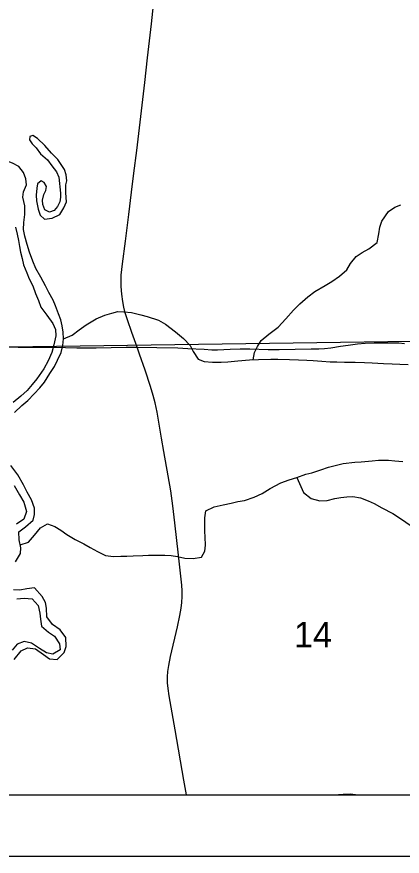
# Model space of a CAD drawing. Extents: x 0 to 34, y 0 to 22.
# Drawn here: x 7.232 to 7.861, y 14 to 15.371 of the extents above; entities that cross this region are included whole.
import ezdxf

# ---------------------------------------------------------------- set-up
doc = ezdxf.new("R2010")
doc.units = 0
for name, color, linetype in [('Default', 7, 'Continuous'), ('GM_X_Interstate_Route', 7, 'Continuous'), ('GM_X_Major_River', 7, 'Continuous'), ('GM_X_Minor_Lake', 7, 'Continuous'), ('GM_X_Minor_River', 7, 'Continuous'), ('GM_X_Section_Text', 7, 'Continuous'), ('GM_X_Township_Road', 7, 'Continuous'), ('SH_Cut_Line', 7, 'Continuous'), ('SH_Data', 7, 'Continuous')]:
    doc.layers.add(name, color=color, linetype=linetype)

msp = doc.modelspace()

# ---------------------------------------------------------------- linework, layer by layer
at = {"layer": 'Default'}
msp.add_lwpolyline([(7.1737, 14.1), (8.2548, 14.1), (8.263, 14.8458), (7.1806, 14.8307)], close=True, dxfattribs=at)
at = {"layer": 'GM_X_Interstate_Route'}
msp.add_lwpolyline([(3.2011, 14.1), (8.2568, 14.1)], dxfattribs=at)
at = {"layer": 'GM_X_Major_River'}
for points in [[(7.242, 15.0762), (7.2431, 15.0852), (7.2482, 15.0966), (7.2471, 15.1065), (7.243, 15.1164), (7.2355, 15.1263), (7.225, 15.1317), (7.214, 15.1364)], [(7.2286, 14.7244), (7.2403, 14.7362), (7.2505, 14.7442), (7.2607, 14.7553), (7.2698, 14.7648), (7.2777, 14.7743), (7.2864, 14.7884), (7.2936, 14.7998), (7.2989, 14.8104), (7.3045, 14.8229), (7.3075, 14.8343), (7.3086, 14.845), (7.3078, 14.856), (7.3063, 14.8662), (7.304, 14.8761), (7.3002, 14.8859), (7.2952, 14.8988), (7.2914, 14.9083), (7.2845, 14.9208), (7.2792, 14.9314), (7.2716, 14.9458), (7.2632, 14.9598), (7.2582, 14.9719), (7.2528, 14.9867), (7.249, 14.9988), (7.2456, 15.0129), (7.2433, 15.0235), (7.244, 15.0352), (7.2455, 15.0482), (7.2454, 15.0622), (7.242, 15.0762)], [(7.23, 15.0272), (7.2327, 15.0162), (7.2353, 15.0056), (7.2365, 14.9958), (7.2384, 14.9863), (7.2411, 14.976), (7.2434, 14.9658), (7.2488, 14.9529), (7.2526, 14.9431), (7.2583, 14.9317), (7.2629, 14.9192), (7.2675, 14.9078), (7.2717, 14.8968), (7.2812, 14.8836), (7.2911, 14.87), (7.2953, 14.8601), (7.2961, 14.8499), (7.2927, 14.835), (7.2894, 14.8225), (7.2837, 14.8092), (7.2762, 14.7959), (7.2652, 14.7799), (7.2573, 14.7704), (7.249, 14.7605), (7.2387, 14.7514), (7.2266, 14.7411)], [(7.23, 14.4808), (7.2383, 14.4942), (7.2391, 14.5036), (7.236, 14.5169), (7.2356, 14.5298), (7.2466, 14.5378), (7.2591, 14.5489), (7.2613, 14.5583), (7.2609, 14.5686), (7.2563, 14.5822), (7.2494, 14.5947), (7.2433, 14.6065), (7.2342, 14.6228), (7.2224, 14.6379)], [(7.2278, 14.6057), (7.2366, 14.5901), (7.2438, 14.578), (7.248, 14.5632), (7.2439, 14.5503), (7.2318, 14.5423)], [(7.2282, 14.3215), (7.2396, 14.3352), (7.2498, 14.3405), (7.2627, 14.3387), (7.2756, 14.3296), (7.2859, 14.3224), (7.298, 14.3213), (7.3098, 14.3327), (7.3131, 14.3426), (7.3123, 14.357), (7.3032, 14.3699), (7.2903, 14.3786), (7.2815, 14.3911), (7.2807, 14.4051), (7.2792, 14.4146), (7.2738, 14.4244), (7.2613, 14.4384), (7.2488, 14.4365), (7.237, 14.4346), (7.2271, 14.4349)], [(7.2321, 14.4205), (7.2442, 14.4213), (7.2575, 14.4202), (7.2674, 14.4092), (7.2701, 14.3971), (7.2709, 14.3873), (7.2725, 14.3759), (7.2839, 14.366), (7.2937, 14.3596), (7.3021, 14.3467), (7.3029, 14.3373), (7.2912, 14.33), (7.2805, 14.3323), (7.2695, 14.3391), (7.2562, 14.3481), (7.2441, 14.3507), (7.2331, 14.3465), (7.2248, 14.3363)]]:
    msp.add_lwpolyline(points, dxfattribs=at)
at = {"layer": 'GM_X_Minor_Lake'}
for points in [[(7.3122, 15.0835), (7.3125, 15.0967), (7.3137, 15.1032), (7.313, 15.113), (7.3101, 15.1214), (7.2992, 15.1378), (7.2887, 15.1485), (7.2779, 15.1608), (7.2662, 15.1723), (7.2583, 15.1769), (7.2534, 15.1755), (7.2529, 15.1698), (7.2574, 15.1637), (7.2638, 15.1571), (7.2709, 15.1472), (7.2822, 15.1372), (7.2897, 15.1273), (7.2972, 15.1177), (7.3009, 15.109), (7.3035, 15.083)], [(7.2765, 15.0809), (7.2799, 15.0875), (7.2807, 15.0936), (7.277, 15.1005), (7.2721, 15.1028), (7.266, 15.0983), (7.2648, 15.0911), (7.264, 15.0797)], [(7.264, 15.0797), (7.2644, 15.0702), (7.2671, 15.0569), (7.2705, 15.0471), (7.2773, 15.0407), (7.2899, 15.0422), (7.3027, 15.0479), (7.3092, 15.059), (7.3133, 15.0688), (7.3122, 15.0835)], [(7.3035, 15.083), (7.3038, 15.0764), (7.3023, 15.0688), (7.2989, 15.0612), (7.2932, 15.0544), (7.2857, 15.0521), (7.2781, 15.0558), (7.275, 15.0642), (7.2742, 15.0714), (7.2765, 15.0809)]]:
    msp.add_lwpolyline(points, dxfattribs=at)
at = {"layer": 'GM_X_Minor_River'}
for points in [[(7.6181, 14.8108), (7.6205, 14.8228), (7.6254, 14.8323), (7.6311, 14.8422), (7.6436, 14.8528), (7.6587, 14.8642), (7.6716, 14.8776), (7.684, 14.892), (7.6943, 14.9023), (7.7071, 14.9137), (7.7185, 14.9221), (7.7355, 14.932), (7.7465, 14.9385), (7.759, 14.9476), (7.7707, 14.9575), (7.7768, 14.9678), (7.7862, 14.9796), (7.7961, 14.9861), (7.807, 14.9922), (7.8203, 15.0021), (7.8233, 15.0165), (7.8248, 15.0271), (7.8281, 15.0374), (7.8387, 15.053), (7.8493, 15.0599), (7.8592, 15.0641)], [(7.3086, 14.8449), (7.3227, 14.8507), (7.334, 14.8595), (7.3457, 14.8678), (7.3617, 14.8774), (7.3757, 14.8835), (7.3874, 14.8869), (7.3973, 14.8896), (7.4068, 14.8893), (7.4193, 14.8878), (7.4348, 14.8844), (7.4451, 14.8814), (7.4633, 14.8754), (7.4751, 14.869), (7.4911, 14.8565), (7.5044, 14.8456), (7.5154, 14.8342), (7.5204, 14.8244), (7.5284, 14.8115), (7.5379, 14.8077), (7.5519, 14.8066), (7.5659, 14.8067), (7.5769, 14.8075), (7.5932, 14.809), (7.6122, 14.8106), (7.627, 14.811), (7.6471, 14.8115), (7.6585, 14.8119), (7.6775, 14.8112), (7.6922, 14.8105), (7.7055, 14.8101), (7.7158, 14.8098), (7.7302, 14.8087), (7.7435, 14.8076), (7.7545, 14.8072), (7.767, 14.8069), (7.7844, 14.8066), (7.7996, 14.8062), (7.8125, 14.8059), (7.8307, 14.8048), (7.8448, 14.8041), (7.8577, 14.8038), (7.8713, 14.803)], [(7.238, 14.5085), (7.2512, 14.5128), (7.261, 14.5242), (7.2708, 14.5364), (7.2826, 14.5429), (7.2944, 14.5387), (7.3042, 14.5327), (7.3141, 14.5255), (7.3274, 14.5172), (7.3419, 14.51), (7.3521, 14.5044), (7.3639, 14.4979), (7.3768, 14.4912), (7.3901, 14.4897), (7.4022, 14.4901), (7.4117, 14.4901), (7.422, 14.4905), (7.4379, 14.4913), (7.4474, 14.4918), (7.4629, 14.4914), (7.4739, 14.4918), (7.4842, 14.4911), (7.4948, 14.4896), (7.5066, 14.487), (7.5202, 14.4863), (7.5339, 14.4882), (7.5391, 14.4981), (7.5403, 14.508), (7.5398, 14.5209), (7.5394, 14.5311), (7.5394, 14.5414), (7.539, 14.5524), (7.5409, 14.5641), (7.5545, 14.5706), (7.5689, 14.5737), (7.5822, 14.5768), (7.5932, 14.5791), (7.6038, 14.581), (7.6197, 14.5864), (7.6326, 14.5921), (7.6458, 14.6005), (7.6632, 14.6097), (7.6769, 14.6146), (7.6894, 14.6185), (7.7042, 14.6242), (7.714, 14.6261), (7.7284, 14.6311), (7.7409, 14.6353), (7.7542, 14.6388), (7.7652, 14.6411), (7.7838, 14.6434), (7.7944, 14.6442), (7.8122, 14.6458), (7.8225, 14.6466), (7.8391, 14.6466), (7.8494, 14.6459), (7.8623, 14.6444)], [(7.6894, 14.6185), (7.7001, 14.5938), (7.713, 14.584), (7.7267, 14.5806), (7.7388, 14.5807), (7.7513, 14.5841), (7.7612, 14.586), (7.771, 14.5868), (7.7805, 14.5876), (7.793, 14.5854), (7.8056, 14.5805), (7.8155, 14.576), (7.828, 14.5692), (7.8462, 14.5597), (7.8618, 14.5492), (7.8725, 14.5416), (7.8858, 14.5329), (7.8979, 14.5269), (7.9074, 14.5224), (7.9215, 14.5148), (7.931, 14.5107), (7.9405, 14.5073), (7.956, 14.4994), (7.9701, 14.4911)], [(7.7493, 14.1), (7.7493, 14.1), (7.7649, 14.1015), (7.7766, 14.1016), (7.7894, 14.1)]]:
    msp.add_lwpolyline(points, dxfattribs=at)
at = {"layer": 'GM_X_Township_Road'}
for points in [[(7.4285, 14.8312), (7.4201, 14.8553), (7.4131, 14.8759), (7.4094, 14.8877), (7.4071, 14.8968), (7.4053, 14.9059), (7.4036, 14.9182), (7.4026, 14.9305), (7.4024, 14.9398), (7.4028, 14.9491), (7.4047, 14.9677), (7.4096, 15.0046), (7.415, 15.0478), (7.4196, 15.0848), (7.4235, 15.1156), (7.4283, 15.1525), (7.4371, 15.2265), (7.4413, 15.2636), (7.4457, 15.3037), (7.4522, 15.3592), (7.4592, 15.4272)], [(7.4285, 14.8312), (7.4607, 14.8309), (7.495, 14.8301), (7.5116, 14.8294), (7.5381, 14.828), (7.5508, 14.8271), (7.5601, 14.8272), (7.5807, 14.8283), (7.5971, 14.8288), (7.6124, 14.8284), (7.6424, 14.8274), (7.6603, 14.8273), (7.7125, 14.8285), (7.7189, 14.8286), (7.7254, 14.8289), (7.7343, 14.8294), (7.745, 14.8305), (7.7608, 14.8329), (7.773, 14.8347), (7.7883, 14.8369), (7.8006, 14.8379), (7.8158, 14.8382), (7.8342, 14.8384), (7.8435, 14.8384), (7.8558, 14.8382), (7.8651, 14.8374)], [(7.2004, 14.8318), (7.2345, 14.8316), (7.2965, 14.8312), (7.312, 14.831), (7.3304, 14.8301), (7.3492, 14.8301), (7.3617, 14.8305), (7.4107, 14.8311), (7.4285, 14.8312)], [(7.5093, 14.1), (7.5051, 14.124), (7.4909, 14.2066), (7.4811, 14.2617), (7.4792, 14.274), (7.4784, 14.2833), (7.4785, 14.2929), (7.4789, 14.3019), (7.4804, 14.3113), (7.4834, 14.3261), (7.4947, 14.3748), (7.4983, 14.3931), (7.5003, 14.4053), (7.5014, 14.4146), (7.502, 14.4239), (7.502, 14.4332), (7.5014, 14.4425), (7.4962, 14.4919), (7.4902, 14.5443), (7.4872, 14.5721), (7.4835, 14.5967), (7.4796, 14.6212), (7.4724, 14.6611), (7.4686, 14.6826), (7.4614, 14.7252), (7.4581, 14.7404), (7.455, 14.7524), (7.4506, 14.7673), (7.4416, 14.7937), (7.4325, 14.8201), (7.4285, 14.8312)]]:
    msp.add_lwpolyline(points, dxfattribs=at)
at = {"layer": 'SH_Cut_Line'}
msp.add_lwpolyline([(2.1, 14.1), (8.2568, 14.1)], dxfattribs=at)
at = {"layer": 'SH_Data'}
for p, q in [((2.1, 14.1), (8.9, 14.1)), ((2, 14), (9, 14))]:
    msp.add_line(p, q, dxfattribs=at)

# ---------------------------------------------------------------- texts
at = {"layer": 'GM_X_Section_Text'}
msp.add_text('14', height=0.04186, rotation=0, dxfattribs=at).set_placement((7.6846, 14.3409))

doc.saveas('drawing.dxf')
